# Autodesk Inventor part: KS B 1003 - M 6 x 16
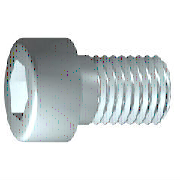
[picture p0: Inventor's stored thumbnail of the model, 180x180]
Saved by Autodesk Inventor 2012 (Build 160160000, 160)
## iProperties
Created: 2009-02
Part Number: KS B 1003 - M 6 x 16
Material: Steel, Mild
Description: 6각머리 태핑 나사
Document SubType Name: Modeling
Standard: KS B 1003
Designer: KYOUNG IL JANG
Standards Organization: KS
Language: ko-KR
Size Designation: M 6 x 16
Categories: <MemberInstance><Categories><Category DisplayName="조임쇠" InternalName="e4da775c-781d-43d5-af7c-5136215cf5a6" Mnemonic="FSTN"><Category DisplayName="볼트" InternalN
Density: 1 g/cm^3
Company: 한국ATC센터
IsCustomPart: 0
Author: KYOUNG IL JANG
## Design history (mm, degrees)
body "Solid1"
workplane "Work Plane1"
fillet "Fillet2" dims "d30" = 0.1 (= R)
revolve "본체" stored, may be unused: angle "d10" = 90 deg
sketch "스케치2"
  geometry: L1 (0, -7)-(0, 7) reference; L2 (-7, 0)-(7, 0) reference; L3 (2.887, 0)-(1.443, -2.5); L4 (1.443, -2.5)-(-1.443, -2.5); L5 (-1.443, -2.5)-(-2.887, 0); L6 (-2.887, 0)-(-1.443, 2.5); L7 (-1.443, 2.5)-(1.443, 2.5); L8 (1.443, 2.5)-(2.887, 0); 2 further points
  constraints: 12 end point, 1 coincident, 1 horizontal alignment, 1 point on line, 12 other
extrude "슬롯" join sketch "스케치2" stored distance "d11" = 10; taper "d12" = 0 deg
fillet "모깎기1" dims "d17" = 0.6 (= RR)
feature "스레드" dims "d13" = 13.5 (= GEL), "d14" = 0
chamfer "모따기1" distance "d15" = 0.61345 (= -0.5 x SPD + 0.5 x GD); stored, may be unused: second distance "d16" = 0.61345 (= GUL), angle "d27" = 45 deg
sketch "스케치1"
  geometry: L1 (-1.333, 0)-(16, 0); L2 (16, 0)-(16, 3); L3 (16, 3)-(2.5, 3); L4 (2.5, 3)-(1.886, 3); L5 (1.886, 3)-(0, 3); L6 (0, 3)-(0, 5); L7 (0, 5)-(-6, 5); L8 (-6, 5)-(-6, 2.887); L9 (-6, 2.887)-(-3, 2.887); L10 (-3, 2.887)-(-1.333, 0); L11 (-10.4, 0)-(20.4, 0) reference; L12 (0, -1)-(0, 6) reference; L13 (2.5, 3)-(0, 3)
  constraints: 22 end point, 6 parallel, 2 collinear, 2 perpendicular, 1 horizontal, 1 point on line
  dimensions: "d1" = 13.5 distance from line of L3.end L2 (= GEL); "d2" = 0.61355 distance of L4.end L3.end (computed from GAL); "d3" = 6 distance between parallel lines of L8 L6 (= KOH); "d4" = 3 distance of L8.end L9.end (= INTI); "d5" = 60 deg angle of L10 L1; "d6" = 6 diameter of L3 L1 (= GD); "d7" = 6 diameter of L5 L1 (= BDM); "d8" = 5.7735 diameter of L9 L1 (= 1.1547 x SW); "d9" = 10 diameter of L7 L1 (= KOD); "d26" = 16 distance between parallel lines of L12 L2 (= NLG)
other parameters: "GD" = 6 (= NND) [user parameter; used in 2 equation terms], "NLG" = 16 [user parameter; used in 1 equation term], "GEL" = 13.5 [user parameter; used in 2 equation terms], "KOD" = 10 [user parameter; used in 1 equation term], "KOH" = 6 [user parameter; used in 1 equation term], "INTI" = 3 [user parameter; used in 1 equation term], "GAL" = 0.61345 (= 0.61345 x PTC) [user parameter; used in 1 equation term], "GUL" = 0.61345 (= 0.61345 x PTC) [user parameter; used in 1 equation term], "BDM" = 6 (= NND) [user parameter; used in 1 equation term], "SW" = 5 [user parameter; used in 2 equation terms], "RR" = 0.6 [user parameter; used in 1 equation term], "SPD" = 4.7731 (= NND - 1.2269 x PTC) [user parameter; used in 1 equation term], "d19" = 0, "d28" = 0, "d29" = 0, "R" = 0.1 [user parameter; used in 1 equation term], "PHH" = 0.25 [user parameter], "GD1" = 4.7731 (= THREADDIA - 1.2269 x PTC) [user parameter], "THREADDIA" = 6 [user parameter; used in 1 equation term], "FAWI" = 45 deg [user parameter], "PTC" = 1 [user parameter; used in 5 equation terms], "NND" = 6 [user parameter; used in 3 equation terms], "TOA" = 30 deg [user parameter], "E0" = 5.775 (= 1.155 x SW) [user parameter]
